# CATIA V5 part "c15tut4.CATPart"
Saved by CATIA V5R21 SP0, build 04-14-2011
Part number: Part1
Bounding box of the stored display mesh (mm): x -3 to 154, y -3 to 154, z -47 to 3.015
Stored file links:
  D:\CATIA V5R21 E-RESOURCES\CATIA-V5R21\catia-v5r21-prt\c15-catia-v5r20-prt\c15-catia-v5r21-tut04.CATPart
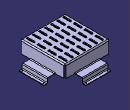
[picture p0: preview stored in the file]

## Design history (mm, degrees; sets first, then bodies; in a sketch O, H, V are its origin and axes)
SheetMetalParameters1: Thickness 1, BendRadius 2, KFactor 0.400515 {= log(min(100,max(20*SheetMetalParameters1.BendRadius,SheetMetalParameters1.Thickness)/SheetMetalParameters1.Thickness))/log(100)/2}, ReliefRadialLength 1, ReliefAxialLength 2, MinimumBendRadius 0
Body1 (main body)
  Sketch1 on xy-plane, origin (0, 0, 0), H (1, 0, 0), V (0, 1, 0)
    line L1 (0, 0) -> (120, 0)
    line L2 (120, 0) -> (120, 120)
    line L3 (120, 120) -> (0, 120)
    line L4 (0, 120) -> (0, 0)
    length L3 = 120
    length L2 = 120
    horizontal: L1 H, L3 H
    vertical: L2 V, L4 V
  Wall1: Thickness 1, Profile Sketch1
  Flange1: Angle 90, Length 34, Radius 2, KFacteur 0.400515 {= log(min(100,max(20*Flange1.Radius,SheetMetalParameters1.Thickness)/SheetMetalParameters1.Thickness))/log(100)/2}, Guide edge [face of Wall1 | face of Wall1]
  Flange2: Angle 90, Length 34, Radius 2, KFacteur 0.400515 {= log(min(100,max(20*Flange2.Radius,SheetMetalParameters1.Thickness)/SheetMetalParameters1.Thickness))/log(100)/2}, Guide edge [face of Wall1 | face of Wall1]
  Flange3: Angle 90, Length 34, Radius 2, KFacteur 0.400515 {= log(min(100,max(20*Flange3.Radius,SheetMetalParameters1.Thickness)/SheetMetalParameters1.Thickness))/log(100)/2}, Guide edge [face of Wall1 | face of Wall1]
  Flange4: Angle 90, Length 34, Radius 2, KFacteur 0.400515 {= log(min(100,max(20*Flange4.Radius,SheetMetalParameters1.Thickness)/SheetMetalParameters1.Thickness))/log(100)/2}, Guide edge [face of Wall1 | face of Wall1]
  d_NewWallOnEdge1: NewWallOnEdge_Edge edge [face of Flange3 | face of Flange3], NewWallOnEdge_Length 21, NewWallOnEdge_HeightLimitOffset 0, NewWallOnEdge_WidthOffset1 -25, NewWallOnEdge_WidthOffset2 -25, NewWallOnEdge_Angle 90, NewWallOnEdge_BendRadiusValue 2 {= SheetMetalParameters1.BendRadius}, NewWallOnEdge_BendTable SheetMetalParameters1, KFacteur 0.400515 {= log(min(100,max(20*d_NewWallOnEdge1.Radius,SheetMetalParameters1.Thickness)/SheetMetalParameters1.Thickness))/log(100)/2}
  Flange5: Angle 90, Length 13, Radius 1, KFacteur 0.325257 {= log(min(100,max(20*Flange5.Radius,SheetMetalParameters1.Thickness)/SheetMetalParameters1.Thickness))/log(100)/2}, Guide edge [face of d_NewWallOnEdge1 | face of d_NewWallOnEdge1]
  d_NewWallOnEdge2: NewWallOnEdge_Edge edge [face of Flange5 | face of Flange5], NewWallOnEdge_Length 10, NewWallOnEdge_HeightLimitOffset 0, NewWallOnEdge_WidthOffset1 0, NewWallOnEdge_WidthOffset2 0, NewWallOnEdge_Angle 90, NewWallOnEdge_BendRadiusValue 2 {= SheetMetalParameters1.BendRadius}, NewWallOnEdge_BendTable SheetMetalParameters1, KFacteur 0.400515 {= log(min(100,max(20*d_NewWallOnEdge2.Radius,SheetMetalParameters1.Thickness)/SheetMetalParameters1.Thickness))/log(100)/2}
  d_NewWallOnEdge3: NewWallOnEdge_Edge edge [face of Flange2 | face of Flange2], NewWallOnEdge_Length 21, NewWallOnEdge_HeightLimitOffset 0, NewWallOnEdge_WidthOffset1 -25, NewWallOnEdge_WidthOffset2 -25, NewWallOnEdge_Angle 90, NewWallOnEdge_BendRadiusValue 2 {= SheetMetalParameters1.BendRadius}, NewWallOnEdge_BendTable SheetMetalParameters1, KFacteur 0.400515 {= log(min(100,max(20*d_NewWallOnEdge3.Radius,SheetMetalParameters1.Thickness)/SheetMetalParameters1.Thickness))/log(100)/2}
  Flange6: Angle 90, Length 13, Radius 1, KFacteur 0.325257 {= log(min(100,max(20*Flange6.Radius,SheetMetalParameters1.Thickness)/SheetMetalParameters1.Thickness))/log(100)/2}, Guide edge [face of d_NewWallOnEdge3 | face of d_NewWallOnEdge3]
  d_NewWallOnEdge4: NewWallOnEdge_Edge edge [face of Flange6 | face of Flange6], NewWallOnEdge_Length 10, NewWallOnEdge_HeightLimitOffset 0, NewWallOnEdge_WidthOffset1 0, NewWallOnEdge_WidthOffset2 0, NewWallOnEdge_Angle 90, NewWallOnEdge_BendRadiusValue 2 {= SheetMetalParameters1.BendRadius}, NewWallOnEdge_BendTable SheetMetalParameters1, KFacteur 0.400515 {= log(min(100,max(20*d_NewWallOnEdge4.Radius,SheetMetalParameters1.Thickness)/SheetMetalParameters1.Thickness))/log(100)/2}
  Sketch2 on face of d_NewWallOnEdge2, origin (31.3691, 147.6369, -46), H (1, 0, 0), V (0, 1, 0)
    point P1 (-1.3691, 2.3631)
    reference projected line E1 (-6.3691, 6.3631) -> (63.6309, 6.3631) from edge [face of d_NewWallOnEdge2 | face of d_NewWallOnEdge2]
    reference projected line E2 (-6.3691, -0.6369) -> (-6.3691, 6.3631) from edge [face of d_NewWallOnEdge2 | face of d_NewWallOnEdge2]
    distance P1 E1 = 4
    distance P1 E2 = 5
  Hole1: placed by Sketch2, at (30, 150, -46) direction (0, 0, -1), diameter 3, through (limit type 6)
  Sketch3 on face of d_NewWallOnEdge2, origin (79.2942, 150.7856, -46), H (1, 0, 0), V (0, 1, 0)
    point P1 (10.7058, -0.7856)
    reference projected line E1 (-54.2942, 3.2144) -> (15.7058, 3.2144) from edge [face of d_NewWallOnEdge2 | face of d_NewWallOnEdge2]
    reference projected line E2 (15.7058, 3.2144) -> (15.7058, -3.7856) from edge [face of d_NewWallOnEdge2 | face of d_NewWallOnEdge2]
    distance P1 E1 = 4
    distance P1 E2 = 5
  Hole2: placed by Sketch3, at (90, 150, -46) direction (0, 0, -1), diameter 3, through (limit type 6)
  Sketch4 on face of d_NewWallOnEdge4, origin (148.0642, 84.3582, -46), H (1, 0, 0), V (0, 1, 0)
    point P1 (1.9358, 5.6418)
    reference projected line E1 (5.9358, 10.6418) -> (5.9358, -59.3582) from edge [face of d_NewWallOnEdge4 | face of d_NewWallOnEdge4]
    reference projected line E2 (-1.0642, 10.6418) -> (5.9358, 10.6418) from edge [face of d_NewWallOnEdge4 | face of d_NewWallOnEdge4]
    distance P1 E1 = 4
    distance P1 E2 = 5
  Hole3: placed by Sketch4, at (150, 90, -46) direction (0, 0, -1), diameter 3, through (limit type 6)
  Sketch5 on face of d_NewWallOnEdge4, origin (149.1042, 61.7681, -46), H (1, 0, 0), V (0, 1, 0)
    point P1 (0.8958, -31.7681)
    reference projected line E1 (4.8958, -36.7681) -> (-2.1042, -36.7681) from edge [face of d_NewWallOnEdge4 | face of d_NewWallOnEdge4]
    reference projected line E2 (4.8958, 33.2319) -> (4.8958, -36.7681) from edge [face of d_NewWallOnEdge4 | face of d_NewWallOnEdge4]
    distance E1 P1 = 5
    distance P1 E2 = 4
  Hole4: placed by Sketch5, at (150, 30, -46) direction (0, 0, -1), diameter 3, through (limit type 6)
  Sketch6 on face of Wall1, origin (0, 0, 0), H (1, 0, 0), V (0, -1, 0)
    line L1 (112, -115) -> (109.5, -115)
    line L2 (109.5, -115) -> (109.5, -95)
    line L3 (109.5, -95) -> (112, -95)
    line L4 (112, -95) -> (112, -115)
    reference projected line E1 (0, -123) -> (120, -123) from edge [face of Flange3 | face of Flange3]
    reference projected line E2 (123, -120) -> (123, 0) from edge [face of Flange2 | face of Flange2]
    distance L2 L4 = 2.5
    length L2 = 20
    distance L1 E1 = 8
    distance L4 E2 = 11
    horizontal: L1 H, L3 H
    vertical: L2 V, L4 V
  d_Stamp1: NewRoot_AttribNormalisation "No Standard", Stamp_FilletRadius 0.25
  RectPattern1: of d_Stamp1, direction 1 instances 7, spacing 17, along edge [face of Flange3 | face of Flange3] reversed, direction 2 instances 4, spacing 30, along edge [face of Flange2 | face of Flange2]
